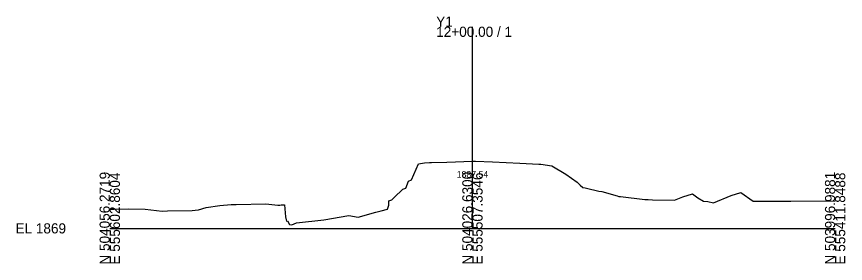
# Model space of a CAD drawing. Extents: x -26 to 1503, y -10 to 5015.
# Drawn here: x -25.7 to 202.8, y 1990.3 to 2058.5 of the extents above; entities that cross this region are included whole.
import ezdxf

# ---------------------------------------------------------------- set-up
doc = ezdxf.new("R2010")
doc.units = 0
for name, color, linetype in [('Default', 7, 'Continuous'), ('Exist Cross Section Cell', 7, 'Continuous'), ('Exist XS Center Line Elevation Label', 7, 'Continuous'), ('Exist XS Ground Line', 7, 'Continuous')]:
    doc.layers.add(name, color=color, linetype=linetype)

msp = doc.modelspace()

# ---------------------------------------------------------------- linework, layer by layer
at = {"layer": 'Exist Cross Section Cell'}
for p, q in [((100, 2000), (100, 2055.69)), ((0, 2000), (100, 2000)), ((100, 2000), (200, 2000))]:
    msp.add_line(p, q, dxfattribs=at)
at = {"layer": 'Exist XS Ground Line'}
for p, q in [((85.17, 2017.8), (86.8, 2018.1)), ((86.8, 2018.1), (88.17, 2018.18)), ((88.17, 2018.18), (88.69, 2018.23)), ((88.69, 2018.23), (92.93, 2018.3)), ((92.93, 2018.3), (100, 2018.54)), ((100, 2018.54), (100.86, 2018.56)), ((100.86, 2018.56), (105.52, 2018.33)), ((105.52, 2018.33), (113.05, 2018.04)), ((113.05, 2018.04), (118.32, 2017.74)), ((83.2, 2013.4), (85.17, 2017.8)), ((118.32, 2017.74), (118.83, 2017.7)), ((118.83, 2017.7), (121.87, 2017.31)), ((121.87, 2017.31), (125.73, 2014.95)), ((82.35, 2013.04), (83.2, 2013.4)), ((125.73, 2014.95), (128.85, 2012.72)), ((80.85, 2010.85), (81.61, 2011.1)), ((81.61, 2011.1), (82.35, 2013.04)), ((128.85, 2012.72), (129.74, 2011.92)), ((129.74, 2011.92), (130.43, 2011.29)), ((130.43, 2011.29), (131.11, 2011.16)), ((131.11, 2011.16), (131.44, 2011.11)), ((131.44, 2011.11), (134.84, 2010.28)), ((78.45, 2008.52), (80.85, 2010.85)), ((134.84, 2010.28), (135.64, 2010.19)), ((135.64, 2010.19), (139.87, 2009.01)), ((139.87, 2009.01), (140.37, 2008.83)), ((140.37, 2008.83), (140.85, 2008.8)), ((157.97, 2008.69), (160.65, 2009.51)), ((160.65, 2009.51), (162.14, 2008.41)), ((166.43, 2007.05), (171.38, 2009.07)), ((171.38, 2009.07), (174.02, 2009.86)), ((174.02, 2009.86), (177.42, 2007.47)), ((30.38, 2006.32), (33.49, 2006.59)), ((33.49, 2006.59), (34.87, 2006.62)), ((34.87, 2006.62), (42.99, 2006.74)), ((42.99, 2006.74), (46.33, 2006.43)), ((76.92, 2006.43), (76.98, 2007.64)), ((76.98, 2007.64), (77.82, 2007.91)), ((77.82, 2007.91), (78.45, 2008.52)), ((140.85, 2008.8), (147.54, 2007.97)), ((147.54, 2007.97), (148.46, 2007.96)), ((148.46, 2007.96), (149.64, 2007.9)), ((149.64, 2007.9), (155.73, 2007.79)), ((155.73, 2007.79), (157.97, 2008.69)), ((162.14, 2008.41), (163.68, 2007.5)), ((163.68, 2007.5), (164.87, 2007.42)), ((164.87, 2007.42), (166.43, 2007.05)), ((177.42, 2007.47), (178.02, 2007.47)), ((178.02, 2007.47), (185.1, 2007.53)), ((185.1, 2007.53), (187.75, 2007.48)), ((187.75, 2007.48), (200, 2007.56)), ((0, 2005.29), (1.14, 2005.29)), ((1.14, 2005.29), (5.12, 2005.35)), ((5.12, 2005.35), (9.8, 2005.27)), ((9.8, 2005.27), (14.49, 2004.72)), ((14.49, 2004.72), (15.95, 2004.81)), ((15.95, 2004.81), (22.68, 2004.92)), ((22.68, 2004.92), (23.54, 2005)), ((23.54, 2005), (24.51, 2005.1)), ((24.51, 2005.1), (26.54, 2005.73)), ((26.54, 2005.73), (30.38, 2006.32)), ((46.33, 2006.43), (46.86, 2006.43)), ((46.86, 2006.43), (47.28, 2006.46)), ((47.28, 2006.46), (48.14, 2006.47)), ((48.14, 2006.47), (48.44, 2003.22)), ((68.46, 2003.13), (73.35, 2004.47)), ((73.35, 2004.47), (74.87, 2004.88)), ((74.87, 2004.88), (76.56, 2005.27)), ((76.56, 2005.27), (76.92, 2006.43)), ((48.44, 2003.22), (48.74, 2002)), ((48.74, 2002), (48.97, 2002.07)), ((48.97, 2002.07), (49.54, 2001.03)), ((51.47, 2001.51), (59.01, 2002.36)), ((59.01, 2002.36), (65.89, 2003.55)), ((65.89, 2003.55), (68.46, 2003.13)), ((49.54, 2001.03), (50.22, 2000.99)), ((50.22, 2000.99), (51.47, 2001.51))]:
    msp.add_line(p, q, dxfattribs=at)

# ---------------------------------------------------------------- texts
at = {"layer": 'Default'}
msp.add_text('-', height=0.0001, dxfattribs=at).set_placement((0, 2000))
at = {"layer": 'Exist Cross Section Cell'}
for s, p in [('Y1', (90, 2055.69)), ('12+00.00 / 1', (90, 2052.89)), ('EL 1869', (-26, 1998.6))]:
    msp.add_text(s, height=2.8, dxfattribs=at).set_placement(p)
for s, p in [('N 504056.2719', (0, 1990)), ('E 555602.8604', (2.8, 1990)), ('N 504026.6300', (100, 1990)), ('E 555507.3546', (102.8, 1990)), ('N 503996.9881', (200, 1990)), ('E 555411.8488', (202.8, 1990))]:
    msp.add_text(s, height=2.8, rotation=90, dxfattribs=at).set_placement(p)
at = {"layer": 'Exist XS Center Line Elevation Label'}
msp.add_text('1887.54', height=1.8, dxfattribs=at).set_placement((95.65, 2014.01))

doc.saveas('drawing.dxf')
